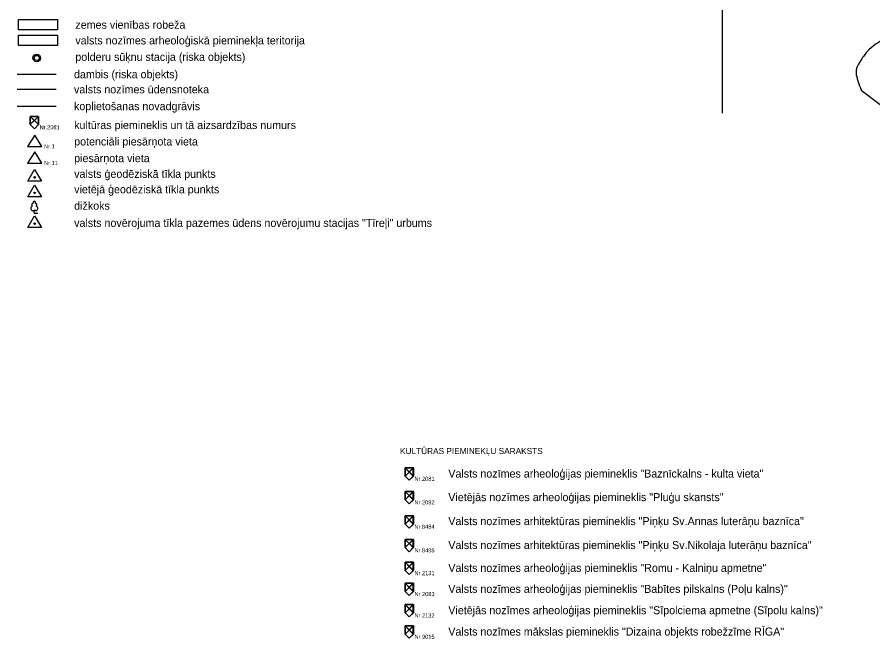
# Model space of a CAD drawing. Extents: x 468834 to 503362, y 294936 to 320859.
# Drawn here: x 475429 to 480974, y 299012 to 303042 of the extents above; entities that cross this region are included whole.
import ezdxf

# ---------------------------------------------------------------- set-up
doc = ezdxf.new("R2010")
doc.units = 0
for name, color, linetype in [('7311080102_vides un dabas resursu aizsardzības aizsargjoslas teritorija ap purvu ar platību lielāku par 100 hektāriem', 7, 'Continuous'), ('7314010202_valsts nozīmes arheoloģiskā pieminekļa teritorija un objekti', 7, 'Continuous'), ('Dambji', 7, 'Continuous'), ('Dižkoki', 7, 'Continuous'), ('Koplietošanas novadgrāvis', 7, 'Continuous'), ('Kulturvesturiskie pieminekļi', 7, 'Continuous'), ('Piesārņota vieta', 7, 'Continuous'), ('Polderu_suknu_stacija', 7, 'Continuous'), ('Potenciāli piesārņota vieta', 7, 'Continuous'), ('ramis', 7, 'Continuous'), ('Teksts', 7, 'Continuous'), ('Valsts novērojuma tīkla pazemes ūdens novērojumu stacijas Tīreļi urbums', 7, 'Continuous'), ('Valsts nozīmes udensnotekas', 7, 'Continuous'), ('Valsts ģeodēziskā tīkla punkts', 7, 'Continuous'), ('Vietējā ģeodēziskā tīkla punkti', 7, 'Continuous'), ('zemes vienības robeža', 7, 'Continuous')]:
    doc.layers.add(name, color=color, linetype=linetype)

msp = doc.modelspace()

# ---------------------------------------------------------------- linework, layer by layer
at = {"layer": '7311080102_vides un dabas resursu aizsardzības aizsargjoslas teritorija ap purvu ar platību lielāku par 100 hektāriem'}
msp.add_line((480898.6, 302568.5), (481020.2, 302475.7), dxfattribs=at)
msp.add_spline([(481135.3, 302930.5), (481105.8, 302921.7), (481045.7, 302897.4), (481017, 302881.6), (480988.7, 302863.8), (480938.7, 302820.3), (480897.9, 302764.7), (480884, 302742.3), (480872.4, 302719.9), (480865.2, 302674.6), (480871, 302648.8), (480878.7, 302623), (480897.6, 302571.3), (480898.6, 302568.5)], degree=3, dxfattribs=at)
at = {"layer": '7314010202_valsts nozīmes arheoloģiskā pieminekļa teritorija un objekti'}
msp.add_lwpolyline([(475437.6, 302924.8), (475691.7, 302924.8), (475691.7, 302858), (475437.6, 302858)], close=True, dxfattribs=at)
at = {"layer": 'Dambji'}
msp.add_line((475429, 302672.2), (475683, 302672.2), dxfattribs=at)
at = {"layer": 'Dižkoki'}
for p, q in [((475540.4, 301771.4), (475540.4, 301787.8)), ((475549.7, 301787.7), (475540.4, 301787.8)), ((475540.4, 301771.4), (475563.4, 301771.4))]:
    msp.add_line(p, q, dxfattribs=at)
for points in [[(475527.5, 301815.8), (475527.4, 301815.8)], [(475532.5, 301835.4), (475532.5, 301835.4), (475532.5, 301835.4), (475532.5, 301835.4)], [(475548.2, 301835.4), (475548.2, 301835.4)], [(475548.2, 301835.4), (475548.2, 301835.4)], [(475548.2, 301835.4), (475548.2, 301835.4)], [(475530.6, 301787.7), (475540.4, 301787.8), (475549.7, 301787.7), (475550.2, 301787.7)]]:
    msp.add_lwpolyline(points, dxfattribs=at)
for centre, major_axis, ratio, start_param, end_param in [((475530.9, 301802), (0, -14.3), 0.937828, 3.40572, 6.25602), ((475532.2, 301824.7), (0, 10.7), 0.78975, 6.245228, 8.827223), ((475530.9, 301802), (0, -14.3), 0.937828, 3.403505, 3.40572), ((475532.2, 301824.7), (0, 10.7), 0.78975, 2.544038, 2.546412), ((475540.4, 301838.9), (0, -9.2), 0.921375, 3.141593, 5.096268), ((475540.4, 301838.9), (0, 9.2), 0.921375, 4.328509, 6.283185), ((475548.6, 301824.7), (0, -10.7), 0.78975, 0.597555, 3.179552), ((475540.4, 301838.9), (0, 9.2), 0.921375, 4.328494, 4.328497), ((475548.6, 301824.7), (0, -10.7), 0.78975, 3.179555, 3.179556), ((475548.6, 301824.7), (0, -10.7), 0.78975, 3.179552, 3.179555), ((475540.4, 301838.9), (0, 9.2), 0.921375, 4.328506, 4.328508), ((475549.8, 301802), (0, 14.3), 0.937828, 3.168748, 6.019057)]:
    msp.add_ellipse(centre, major_axis=major_axis, ratio=ratio, start_param=start_param, end_param=end_param, dxfattribs=at)
at = {"layer": 'Koplietošanas novadgrāvis'}
msp.add_line((475429, 302465.3), (475683, 302465.3), dxfattribs=at)
at = {"layer": 'Kulturvesturiskie pieminekļi'}
for p, q in [((475514.2, 302398.5), (475567.4, 302345.3)), ((475567.4, 302398.5), (475514.2, 302345.3)), ((475514.2, 302398.5), (475567.4, 302398.5)), ((475514.2, 302345.3), (475514.2, 302398.5)), ((475514.4, 302345.3), (475514.4, 302398.5)), ((475514.4, 302398.5), (475567.6, 302345.3)), ((475514.4, 302398.5), (475567.6, 302398.5)), ((475567.6, 302398.5), (475514.4, 302345.3)), ((475567.4, 302398.5), (475567.4, 302345.3)), ((475567.6, 302398.5), (475567.6, 302345.3)), ((475540.8, 302318.7), (475514.2, 302345.3)), ((475541, 302318.7), (475514.4, 302345.3)), ((475567.4, 302345.3), (475540.8, 302318.7)), ((475567.6, 302345.3), (475541, 302318.7)), ((477942.8, 300120.3), (477996.1, 300067)), ((477996.1, 300120.3), (477942.8, 300067)), ((477942.8, 300120.3), (477996.1, 300120.3)), ((477942.8, 300067), (477942.8, 300120.3)), ((477943, 300067), (477943, 300120.3)), ((477943, 300120.3), (477996.2, 300067)), ((477943, 300120.3), (477996.2, 300120.3)), ((477996.2, 300120.3), (477943, 300067)), ((477996.1, 300120.3), (477996.1, 300067)), ((477996.2, 300120.3), (477996.2, 300067)), ((477969.4, 300040.4), (477942.8, 300067)), ((477969.6, 300040.4), (477943, 300067)), ((477996.1, 300067), (477969.4, 300040.4)), ((477996.2, 300067), (477969.6, 300040.4)), ((477942.8, 299967.5), (477996.1, 299914.3)), ((477996.1, 299967.5), (477942.8, 299914.3)), ((477942.8, 299967.5), (477996.1, 299967.5)), ((477942.8, 299914.3), (477942.8, 299967.5)), ((477943, 299914.3), (477943, 299967.5)), ((477943, 299967.5), (477996.2, 299914.3)), ((477943, 299967.5), (477996.2, 299967.5)), ((477996.2, 299967.5), (477943, 299914.3)), ((477996.1, 299967.5), (477996.1, 299914.3)), ((477996.2, 299967.5), (477996.2, 299914.3)), ((477969.4, 299887.6), (477942.8, 299914.3)), ((477969.6, 299887.6), (477943, 299914.3)), ((477996.1, 299914.3), (477969.4, 299887.6)), ((477996.2, 299914.3), (477969.6, 299887.6)), ((477942.8, 299809.8), (477996.1, 299756.5)), ((477996.1, 299809.8), (477942.8, 299756.5)), ((477942.8, 299809.8), (477996.1, 299809.8)), ((477942.8, 299756.5), (477942.8, 299809.8)), ((477943, 299756.5), (477943, 299809.8)), ((477943, 299809.8), (477996.2, 299756.5)), ((477943, 299809.8), (477996.2, 299809.8)), ((477996.2, 299809.8), (477943, 299756.5)), ((477996.1, 299809.8), (477996.1, 299756.5)), ((477996.2, 299809.8), (477996.2, 299756.5)), ((477969.4, 299729.9), (477942.8, 299756.5)), ((477969.6, 299729.9), (477943, 299756.5)), ((477996.1, 299756.5), (477969.4, 299729.9)), ((477996.2, 299756.5), (477969.6, 299729.9)), ((477942.8, 299656.9), (477996.1, 299603.7)), ((477996.1, 299656.9), (477942.8, 299603.7)), ((477942.8, 299656.9), (477996.1, 299656.9)), ((477942.8, 299603.7), (477942.8, 299656.9)), ((477943, 299603.7), (477943, 299656.9)), ((477943, 299656.9), (477996.2, 299603.7)), ((477943, 299656.9), (477996.2, 299656.9)), ((477996.2, 299656.9), (477943, 299603.7)), ((477996.1, 299656.9), (477996.1, 299603.7)), ((477996.2, 299656.9), (477996.2, 299603.7)), ((477969.4, 299577.1), (477942.8, 299603.7)), ((477969.6, 299577.1), (477943, 299603.7)), ((477996.1, 299603.7), (477969.4, 299577.1)), ((477996.2, 299603.7), (477969.6, 299577.1)), ((477942.8, 299508.9), (477996.1, 299455.7)), ((477996.1, 299508.9), (477942.8, 299455.7)), ((477942.8, 299508.9), (477996.1, 299508.9)), ((477942.8, 299455.7), (477942.8, 299508.9)), ((477943, 299455.7), (477943, 299508.9)), ((477943, 299508.9), (477996.2, 299455.7)), ((477943, 299508.9), (477996.2, 299508.9)), ((477996.2, 299508.9), (477943, 299455.7)), ((477996.1, 299508.9), (477996.1, 299455.7)), ((477996.2, 299508.9), (477996.2, 299455.7)), ((477969.4, 299429.1), (477942.8, 299455.7)), ((477969.6, 299429.1), (477943, 299455.7)), ((477996.1, 299455.7), (477969.4, 299429.1)), ((477996.2, 299455.7), (477969.6, 299429.1)), ((477942.8, 299373), (477996.1, 299319.8)), ((477996.1, 299373), (477942.8, 299319.8)), ((477942.8, 299373), (477996.1, 299373)), ((477942.8, 299319.8), (477942.8, 299373)), ((477943, 299319.8), (477943, 299373)), ((477943, 299373), (477996.2, 299319.8)), ((477943, 299373), (477996.2, 299373)), ((477996.2, 299373), (477943, 299319.8)), ((477996.1, 299373), (477996.1, 299319.8)), ((477996.2, 299373), (477996.2, 299319.8)), ((477969.4, 299293.2), (477942.8, 299319.8)), ((477969.6, 299293.2), (477943, 299319.8)), ((477996.1, 299319.8), (477969.4, 299293.2)), ((477996.2, 299319.8), (477969.6, 299293.2)), ((477942.8, 299234.7), (477996.1, 299181.5)), ((477996.1, 299234.7), (477942.8, 299181.5)), ((477942.8, 299234.7), (477996.1, 299234.7)), ((477942.8, 299181.5), (477942.8, 299234.7)), ((477943, 299181.5), (477943, 299234.7)), ((477943, 299234.7), (477996.2, 299181.5)), ((477943, 299234.7), (477996.2, 299234.7)), ((477996.2, 299234.7), (477943, 299181.5)), ((477996.1, 299234.7), (477996.1, 299181.5)), ((477996.2, 299234.7), (477996.2, 299181.5)), ((477969.4, 299154.9), (477942.8, 299181.5)), ((477969.6, 299154.9), (477943, 299181.5)), ((477996.1, 299181.5), (477969.4, 299154.9)), ((477996.2, 299181.5), (477969.6, 299154.9)), ((477942.8, 299096.4), (477996.1, 299043.2)), ((477996.1, 299096.4), (477942.8, 299043.2)), ((477942.8, 299096.4), (477996.1, 299096.4)), ((477942.8, 299043.2), (477942.8, 299096.4)), ((477943, 299043.2), (477943, 299096.4)), ((477943, 299096.4), (477996.2, 299043.2)), ((477943, 299096.4), (477996.2, 299096.4)), ((477996.2, 299096.4), (477943, 299043.2)), ((477996.1, 299096.4), (477996.1, 299043.2)), ((477996.2, 299096.4), (477996.2, 299043.2)), ((477969.4, 299016.6), (477942.8, 299043.2)), ((477969.6, 299016.6), (477943, 299043.2)), ((477996.1, 299043.2), (477969.4, 299016.6)), ((477996.2, 299043.2), (477969.6, 299016.6))]:
    msp.add_line(p, q, dxfattribs=at)
for points in [[(475541, 302371.9), (475567.6, 302398.5), (475514.4, 302398.5), (475541, 302371.9)], [(475541, 302371.9), (475514.4, 302398.5), (475514.4, 302345.3), (475541, 302371.9)], [(475514.4, 302345.5), (475540.8, 302371.9), (475514.4, 302398.3), (475514.4, 302345.5)], [(475541, 302371.9), (475514.4, 302345.3), (475541, 302318.7), (475567.6, 302345.3), (475541, 302371.9)], [(475567.6, 302398.5), (475541, 302371.9), (475567.6, 302345.3), (475567.6, 302398.5)], [(475567.4, 302345.5), (475567.4, 302398.3), (475541, 302371.9), (475567.4, 302345.5)], [(477969.6, 300093.6), (477996.2, 300120.3), (477943, 300120.3), (477969.6, 300093.6)], [(477969.6, 300093.6), (477943, 300120.3), (477943, 300067), (477969.6, 300093.6)], [(477943, 300067.2), (477969.4, 300093.6), (477943, 300120.1), (477943, 300067.2)], [(477969.6, 300093.6), (477943, 300067), (477969.6, 300040.4), (477996.2, 300067), (477969.6, 300093.6)], [(477996.2, 300120.3), (477969.6, 300093.6), (477996.2, 300067), (477996.2, 300120.3)], [(477996.1, 300067.2), (477996.1, 300120.1), (477969.6, 300093.6), (477996.1, 300067.2)], [(477969.6, 299940.9), (477996.2, 299967.5), (477943, 299967.5), (477969.6, 299940.9)], [(477969.6, 299940.9), (477943, 299967.5), (477943, 299914.3), (477969.6, 299940.9)], [(477943, 299914.4), (477969.4, 299940.9), (477943, 299967.3), (477943, 299914.4)], [(477969.6, 299940.9), (477943, 299914.3), (477969.6, 299887.6), (477996.2, 299914.3), (477969.6, 299940.9)], [(477996.2, 299967.5), (477969.6, 299940.9), (477996.2, 299914.3), (477996.2, 299967.5)], [(477996.1, 299914.4), (477996.1, 299967.3), (477969.6, 299940.9), (477996.1, 299914.4)], [(477969.6, 299783.2), (477996.2, 299809.8), (477943, 299809.8), (477969.6, 299783.2)], [(477969.6, 299783.2), (477943, 299809.8), (477943, 299756.5), (477969.6, 299783.2)], [(477943, 299756.7), (477969.4, 299783.2), (477943, 299809.6), (477943, 299756.7)], [(477996.2, 299809.8), (477969.6, 299783.2), (477996.2, 299756.5), (477996.2, 299809.8)], [(477996.1, 299756.7), (477996.1, 299809.6), (477969.6, 299783.2), (477996.1, 299756.7)], [(477969.6, 299783.2), (477943, 299756.5), (477969.6, 299729.9), (477996.2, 299756.5), (477969.6, 299783.2)], [(477969.6, 299630.3), (477996.2, 299656.9), (477943, 299656.9), (477969.6, 299630.3)], [(477969.6, 299630.3), (477943, 299656.9), (477943, 299603.7), (477969.6, 299630.3)], [(477943, 299603.9), (477969.4, 299630.3), (477943, 299656.7), (477943, 299603.9)], [(477996.2, 299656.9), (477969.6, 299630.3), (477996.2, 299603.7), (477996.2, 299656.9)], [(477996.1, 299603.9), (477996.1, 299656.7), (477969.6, 299630.3), (477996.1, 299603.9)], [(477969.6, 299630.3), (477943, 299603.7), (477969.6, 299577.1), (477996.2, 299603.7), (477969.6, 299630.3)], [(477969.6, 299482.3), (477996.2, 299508.9), (477943, 299508.9), (477969.6, 299482.3)], [(477969.6, 299482.3), (477943, 299508.9), (477943, 299455.7), (477969.6, 299482.3)], [(477943, 299455.9), (477969.4, 299482.3), (477943, 299508.7), (477943, 299455.9)], [(477969.6, 299482.3), (477943, 299455.7), (477969.6, 299429.1), (477996.2, 299455.7), (477969.6, 299482.3)], [(477996.2, 299508.9), (477969.6, 299482.3), (477996.2, 299455.7), (477996.2, 299508.9)], [(477996.1, 299455.9), (477996.1, 299508.7), (477969.6, 299482.3), (477996.1, 299455.9)], [(477969.6, 299346.4), (477996.2, 299373), (477943, 299373), (477969.6, 299346.4)], [(477969.6, 299346.4), (477943, 299373), (477943, 299319.8), (477969.6, 299346.4)], [(477943, 299320), (477969.4, 299346.4), (477943, 299372.9), (477943, 299320)], [(477996.2, 299373), (477969.6, 299346.4), (477996.2, 299319.8), (477996.2, 299373)], [(477996.1, 299320), (477996.1, 299372.9), (477969.6, 299346.4), (477996.1, 299320)], [(477969.6, 299346.4), (477943, 299319.8), (477969.6, 299293.2), (477996.2, 299319.8), (477969.6, 299346.4)], [(477969.6, 299208.1), (477996.2, 299234.7), (477943, 299234.7), (477969.6, 299208.1)], [(477969.6, 299208.1), (477943, 299234.7), (477943, 299181.5), (477969.6, 299208.1)], [(477943, 299181.7), (477969.4, 299208.1), (477943, 299234.6), (477943, 299181.7)], [(477969.6, 299208.1), (477943, 299181.5), (477969.6, 299154.9), (477996.2, 299181.5), (477969.6, 299208.1)], [(477996.2, 299234.7), (477969.6, 299208.1), (477996.2, 299181.5), (477996.2, 299234.7)], [(477996.1, 299181.7), (477996.1, 299234.6), (477969.6, 299208.1), (477996.1, 299181.7)], [(477969.6, 299069.8), (477996.2, 299096.4), (477943, 299096.4), (477969.6, 299069.8)], [(477969.6, 299069.8), (477943, 299096.4), (477943, 299043.2), (477969.6, 299069.8)], [(477943, 299043.4), (477969.4, 299069.8), (477943, 299096.3), (477943, 299043.4)], [(477996.2, 299096.4), (477969.6, 299069.8), (477996.2, 299043.2), (477996.2, 299096.4)], [(477996.1, 299043.4), (477996.1, 299096.3), (477969.6, 299069.8), (477996.1, 299043.4)], [(477969.6, 299069.8), (477943, 299043.2), (477969.6, 299016.6), (477996.2, 299043.2), (477969.6, 299069.8)]]:
    msp.add_lwpolyline(points, dxfattribs=at)
at = {"layer": 'Piesārņota vieta'}
for p, q in [((475542.7, 302169.5), (475496.4, 302094.8)), ((475588.9, 302094.8), (475542.7, 302169.5)), ((475496.4, 302094.8), (475588.9, 302094.8))]:
    msp.add_line(p, q, dxfattribs=at)
at = {"layer": 'Polderu_suknu_stacija'}
for radius in [24.3, 16.2]:
    msp.add_circle((475556, 302777.1), radius, dxfattribs=at)
at = {"layer": 'Potenciāli piesārņota vieta'}
for p, q in [((475542.7, 302277.5), (475496.4, 302202.8)), ((475588.9, 302202.8), (475542.7, 302277.5)), ((475496.4, 302202.8), (475588.9, 302202.8))]:
    msp.add_line(p, q, dxfattribs=at)
at = {"layer": 'ramis'}
msp.add_line((480000, 302419), (480000, 315463.3), dxfattribs=at)
at = {"layer": 'Valsts novērojuma tīkla pazemes ūdens novērojumu stacijas Tīreļi urbums'}
for p, q in [((475499, 301678.3), (475542.5, 301753.7)), ((475542.5, 301753.7), (475586.1, 301678.3)), ((475586.1, 301678.3), (475499, 301678.3))]:
    msp.add_line(p, q, dxfattribs=at)
msp.add_circle((475542.5, 301703.4), 4.84, dxfattribs=at)
at = {"layer": 'Valsts nozīmes udensnotekas'}
msp.add_line((475429, 302574.2), (475683, 302574.2), dxfattribs=at)
at = {"layer": 'Valsts ģeodēziskā tīkla punkts'}
for p, q in [((475499, 301977.8), (475542.5, 302053.3)), ((475542.5, 302053.3), (475586.1, 301977.8)), ((475586.1, 301977.8), (475499, 301977.8))]:
    msp.add_line(p, q, dxfattribs=at)
msp.add_circle((475542.5, 302003), 4.84, dxfattribs=at)
at = {"layer": 'Vietējā ģeodēziskā tīkla punkti'}
for p, q in [((475499, 301877.5), (475542.5, 301953)), ((475542.5, 301953), (475586.1, 301877.5)), ((475586.1, 301877.5), (475499, 301877.5))]:
    msp.add_line(p, q, dxfattribs=at)
msp.add_circle((475542.5, 301902.7), 4.84, dxfattribs=at)
at = {"layer": 'zemes vienības robeža'}
msp.add_lwpolyline([(475437.6, 303026.5), (475691.7, 303026.5), (475691.7, 302959.7), (475437.6, 302959.7)], close=True, dxfattribs=at)

# ---------------------------------------------------------------- texts
at = {"layer": 'Teksts'}
for s, height, p in [('zemes vienības robeža', 51.84, (475806.3, 302966.5)), ('valsts nozīmes arheoloģiskā pieminekļa teritorija', 51.84, (475806.3, 302864.8)), ('polderu sūķnu stacija (riska objekts)', 51.84, (475806.3, 302758)), ('dambis (riska objekts)', 51.84, (475797.6, 302645.6)), ('valsts nozīmes ūdensnoteka', 51.84, (475797.6, 302547.6)), ('koplietošanas novadgrāvis', 51.84, (475797.6, 302438.7)), ('kultūras piemineklis un tā aizsardzības numurs', 51.84, (475798.6, 302316.3)), ('Nr.2081', 26.54, (475574.8, 302314.9)), ('potenciāli piesārņota vieta', 51.84, (475798.6, 302209.8)), ('Nr.1', 26.54, (475603.7, 302191.2)), ('piesārņota vieta', 51.84, (475798.6, 302101.8)), ('Nr.11', 26.54, (475603.7, 302083.2)), ('valsts ģeodēziskā tīkla punkts', 51.84, (475798.6, 302000.1)), ('vietējā ģeodēziskā tīkla punkts', 51.84, (475798.6, 301899.9)), ('dižkoks', 51.84, (475798.6, 301793.7)), ('valsts novērojuma tīkla pazemes ūdens novērojumu stacijas "Tīreļi" urbums', 51.84, (475798.6, 301682.2)), ('KULTŪRAS PIEMINEKĻU SARAKSTS', 40, (477910.1, 300210)), ('Valsts nozīmes arheoloģijas piemineklis "Baznīckalns - kulta vieta"', 51.84, (478222.8, 300057.8)), ('Nr.2081', 26.54, (478003.4, 300036.6)), ('Vietējās nozīmes arheoloģijas piemineklis "Pluģu skansts"', 51.84, (478222.8, 299905.1)), ('Nr.2082', 26.54, (478003.4, 299883.9)), ('Nr.8484', 26.54, (478003.4, 299726.2)), ('Valsts nozīmes arhitektūras piemineklis "Piņķu Sv.Annas luterāņu baznīca"', 51.84, (478222.8, 299749.8)), ('Valsts nozīmes arhitektūras piemineklis "Piņķu Sv.Nikolaja luterāņu baznīca"', 51.84, (478222.8, 299594.5)), ('Nr.8485', 26.54, (478003.4, 299573.3)), ('Valsts nozīmes arheoloģijas piemineklis "Romu - Kalniņu apmetne"', 51.84, (478222.8, 299446.5)), ('Nr.2131', 26.54, (478003.4, 299425.3)), ('Valsts nozīmes arheoloģijas piemineklis "Babītes pilskalns (Poļu kalns)"', 51.84, (478222.8, 299310.6)), ('Nr.2083', 26.54, (478003.4, 299289.4)), ('Vietējās nozīmes arheoloģijas piemineklis "Sīpolciema apmetne (Sīpolu kalns)"', 51.84, (478222.8, 299172.3)), ('Nr.2132', 26.54, (478003.4, 299151.1)), ('Valsts nozīmes mākslas piemineklis "Dizaina objekts robežzīme RĪGA"', 51.84, (478222.8, 299034)), ('Nr.9015', 26.54, (478003.4, 299012.8))]:
    msp.add_text(s, height=height, dxfattribs=at).set_placement(p)

doc.saveas('drawing.dxf')
